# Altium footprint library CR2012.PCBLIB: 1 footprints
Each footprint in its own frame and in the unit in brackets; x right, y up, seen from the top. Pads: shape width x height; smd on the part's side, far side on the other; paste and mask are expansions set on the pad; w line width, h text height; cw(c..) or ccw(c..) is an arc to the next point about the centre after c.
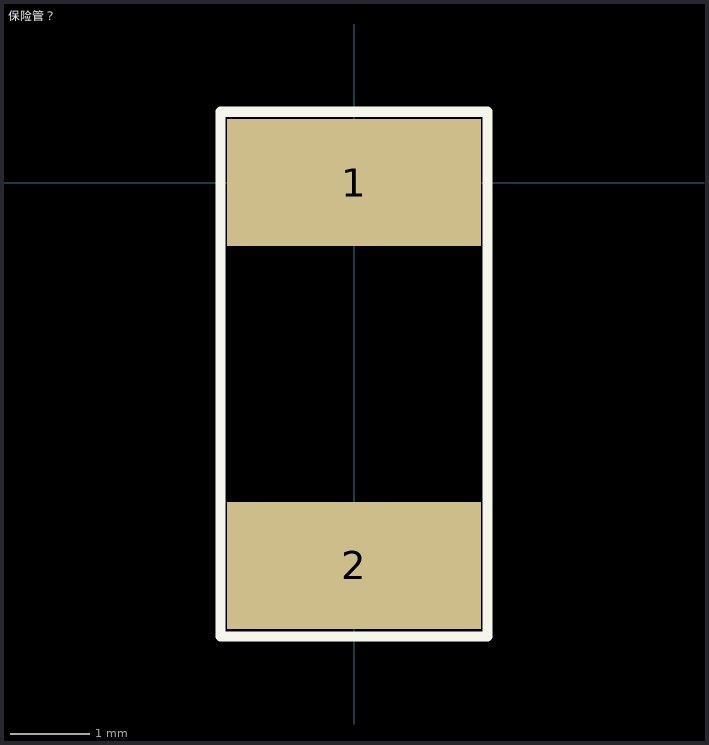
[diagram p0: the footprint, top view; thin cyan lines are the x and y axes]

## 保险管？ [mm]
pads (2):
  rect 3.18x1.59 smd: 1(0,0) 2(0,-4.8)
Top Overlay:
  lines w0.127: 1.651,-5.69 -1.676,-5.69 -1.676,0.889 1.651,0.889 ; 1.676,-5.69 1.676,0.889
